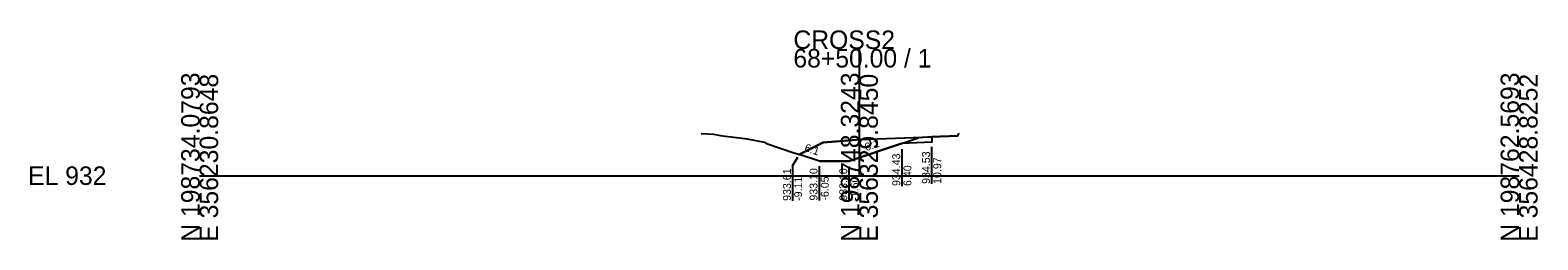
# Model space of a CAD drawing. Extents: x -26 to 203, y -10 to 14021.
# Drawn here: x -25.7 to 202.8, y 9490.3 to 9522 of the extents above; entities that cross this region are included whole.
import ezdxf

# ---------------------------------------------------------------- set-up
doc = ezdxf.new("R2010")
doc.units = 0
for name, color, linetype in [('Default', 7, 'Continuous'), ('P_E_XS_Ground', 7, 'Continuous'), ('P_XS', 7, 'Continuous'), ('P_XS_EAR_CommonGrnd', 7, 'Continuous'), ('P_XS_Lane', 7, 'Continuous'), ('P_XS_Rock', 7, 'Continuous')]:
    doc.layers.add(name, color=color, linetype=linetype)

msp = doc.modelspace()

# ---------------------------------------------------------------- linework, layer by layer
at = {"layer": 'Default'}
for p, q in [((100, 9500), (100, 9519.16)), ((0, 9500), (100, 9500)), ((100, 9500), (200, 9500))]:
    msp.add_line(p, q, dxfattribs=at)
at = {"layer": 'P_E_XS_Ground'}
for p, q in [((76.01, 9506.39), (77.91, 9506.26)), ((77.91, 9506.26), (78.95, 9506.09)), ((78.95, 9506.09), (79.29, 9506.05)), ((79.29, 9506.05), (82.66, 9505.63)), ((82.66, 9505.63), (83.01, 9505.56)), ((83.01, 9505.56), (85.61, 9505.05)), ((85.61, 9505.05), (86.06, 9504.83)), ((86.06, 9504.83), (90.05, 9503.45)), ((94.5, 9505.03), (90.89, 9503.22)), ((99.5, 9505.43), (94.5, 9505.03)), ((99.5, 9505.43), (100, 9505.45)), ((100, 9505.45), (114.97, 9506.04)), ((114.97, 9506.35), (115.17, 9506.36)), ((114.97, 9506.04), (114.97, 9506.35)), ((90.05, 9503.45), (90.61, 9503.29)), ((90.61, 9503.29), (90.89, 9503.22))]:
    msp.add_line(p, q, dxfattribs=at)
at = {"layer": 'P_XS'}
for p, q in [((106.4, 9504.87), (108.97, 9505.72)), ((110.97, 9505.88), (108.97, 9505.72)), ((114.97, 9506.04), (110.97, 9505.88))]:
    msp.add_line(p, q, dxfattribs=at)
at = {"layer": 'P_XS_EAR_CommonGrnd'}
msp.add_lwpolyline([(93.95, 9502.2), (90.89, 9503.22), (94.5, 9505.03), (99.5, 9505.43), (100, 9505.45), (110.97, 9505.88), (110.97, 9505.05), (106.4, 9504.87), (98.4, 9502.2)], close=True, dxfattribs=at)
at = {"layer": 'P_XS_Lane'}
for p, q in [((98.4, 9502.2), (106.4, 9504.87)), ((110.97, 9505.05), (106.4, 9504.87)), ((110.97, 9505.88), (110.97, 9505.05)), ((93.95, 9502.2), (90.89, 9503.22)), ((93.95, 9502.2), (98.4, 9502.2))]:
    msp.add_line(p, q, dxfattribs=at)
at = {"layer": 'P_XS_Rock'}
for p, q in [((89.87, 9501.48), (90.66, 9502.82)), ((106.43, 9504.03), (106.43, 9498.43)), ((110.95, 9504.36), (110.95, 9498.76)), ((89.87, 9501.48), (89.87, 9496.19)), ((93.9, 9501.44), (93.9, 9496.23)), ((98.41, 9501.41), (98.41, 9496.2))]:
    msp.add_line(p, q, dxfattribs=at)

# ---------------------------------------------------------------- texts
at = {"layer": 'Default'}
for s, p in [('CROSS2', (90, 9519.16)), ('68+50.00 / 1', (90, 9516.36)), ('EL 932', (-26, 9498.6))]:
    msp.add_text(s, height=2.8, dxfattribs=at).set_placement(p)
for s, p in [('N 198734.0793', (0, 9490)), ('E 356230.8648', (2.8, 9490)), ('N 198748.3243', (100, 9490)), ('E 356329.8450', (102.8, 9490)), ('N 198762.5693', (200, 9490)), ('E 356428.8252', (202.8, 9490))]:
    msp.add_text(s, height=2.8, rotation=90, dxfattribs=at).set_placement(p)
at = {"layer": 'P_XS_Rock'}
for s, rotation, p in [('6:1', 341.5651, (91.58, 9503.74)), ('6:1', 18.4349, (101.03, 9503.7)), ('934.43', 90, (106.18, 9498.44)), ('934.53', 90, (110.7, 9498.76)), ('10.97', 90, (112.4, 9498.76)), ('933.61', 90, (89.62, 9496.19)), ('933.10', 90, (93.65, 9496.23)), ('933.10', 90, (98.16, 9496.21)), ('6.40', 90, (107.88, 9498.44)), ('-9.11', 90, (91.32, 9496.19)), ('-6.05', 90, (95.35, 9496.23)), ('-1.60', 90, (99.86, 9496.21))]:
    msp.add_text(s, height=1.2, rotation=rotation, dxfattribs=at).set_placement(p)

doc.saveas('drawing.dxf')
